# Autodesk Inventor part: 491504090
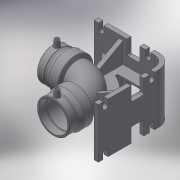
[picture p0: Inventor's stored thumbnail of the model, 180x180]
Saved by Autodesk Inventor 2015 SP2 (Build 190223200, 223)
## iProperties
Created: 2017-06
Part Number: 491504090
Material: Generic
Description: PLASSON DF 90° ELBOW 90
Document SubType Name: Modeling
Designer: KIM
Mass: 55.0731 g
Surface Area: 148.067 cm^2
Volume: 55.0731 cm^3
Density: 1 g/cm^3
Appearance: Default
Author: KIM
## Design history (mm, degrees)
derived "491504.ipt"
feature "Solid1::491504.ipt"
tag "TaggingFeature1"
body "Solid1"
other parameters: "d14" = 17.6296, "d19" = 3.52592, "d20" = 168 deg, "d22" = 103.04, "d23" = 112, "d29" = 71, "d35" = 15, "d39" = 5 deg, "d44" = 9.6, "d45" = 4.8, "d46" = 6, "d47" = 0, "d63" = 147, "d67" = 45 deg, "d71" = 90 deg, "d75" = 5.6, "d82" = 45 deg, "d83" = 69, "d84" = 100.8, "d87" = 26.1, "d88" = 26.1, "d90" = 13.05, "d91" = 33.6, "d92" = 156.8, "d93" = 0, "d94" = 26.1, "d95" = 26.1, "d96" = 50 deg, "d98" = 145.34, "d99" = 5.6, "d100" = 0, "d101" = 4.5, "d102" = 22.4, "d103" = 11.2, "d104" = 11.2, "d105" = 13.05, "d106" = 0, "d107" = 45 deg, "d108" = 33.6, "d110" = 40.19528, "d111" = 146, "d112" = 16, "d113" = 16.8, "d114" = 22.4, "d116" = 0, "d117" = 4.5, "d118" = 115, "d119" = 115, "d121" = 105.56, "d122" = 23, "d123" = 99.9488, "d124" = 4.6, "L_0" = 203, "L_1" = 69, "D_" = 112, "A_" = 71, "d_2" = 12, "L_" = 261, "H_" = 146, "A_1" = 115, "d97" = 111.8, "d120" = 262
